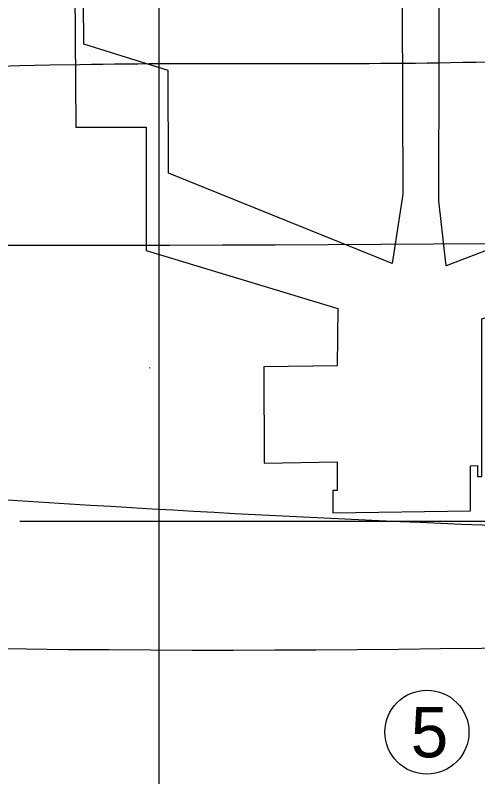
# Model space of a CAD drawing. Extents: x 3042 to 4120, y 576 to 2694.
# Drawn here: x 3407.61 to 3421.37, y 879.91 to 902.59 of the extents above; entities that cross this region are included whole.
import ezdxf

# ---------------------------------------------------------------- set-up
doc = ezdxf.new("R2010")
doc.units = 0
for name, color, linetype in [('HPV', 7, 'Continuous'), ('nádrže', 7, 'Continuous'), ('pomocna', 7, 'Continuous'), ('rozhraní', 7, 'Continuous')]:
    doc.layers.add(name, color=color, linetype=linetype)

msp = doc.modelspace()

# ---------------------------------------------------------------- linework, layer by layer
at = {"layer": 'HPV'}
msp.add_spline([(3335.582962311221, 896.0481503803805), (3352.5717167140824, 896.0481503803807), (3453.0617167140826, 896.509755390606), (3557.3317167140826, 895.7898480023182), (3580.051716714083, 892.4898632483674), (3619.081666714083, 896.3928809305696), (3629.646992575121, 896.3928809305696)], degree=3, dxfattribs=at)
at = {"layer": 'nádrže'}
for points in [[(3409.303423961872, 914.1569885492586), (3409.408686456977, 899.2547771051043), (3411.508241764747, 899.2547771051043), (3411.508241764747, 895.5829811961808), (3417.204521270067, 893.855992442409), (3417.1837969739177, 892.1470730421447), (3415.008440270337, 892.1134452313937), (3415.0102104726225, 889.2506202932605), (3417.18601010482, 889.2842549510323), (3417.186534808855, 888.4356876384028), (3417.053939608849, 888.4336379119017), (3417.054349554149, 887.7706619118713), (3421.1484111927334, 887.8339500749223), (3421.1475844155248, 889.1710393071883), (3421.357533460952, 889.1742848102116), (3421.3577313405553, 888.854267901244), (3421.491589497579, 888.8563371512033), (3421.4886866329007, 893.5509381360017), (3427.7400951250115, 895.7070122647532), (3427.694777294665, 898.9919209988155), (3429.8856289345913, 899.1045903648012), (3429.868067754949, 915.3762984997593)], [(3419.083560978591, 914.0946410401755), (3419.1425912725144, 897.2650842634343), (3418.823963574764, 895.1957636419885), (3412.1724532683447, 897.8815423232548), (3412.161788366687, 900.9398904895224), (3409.6512038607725, 901.7310102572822), (3409.548831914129, 914.2950201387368)], [(3429.622937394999, 914.1473342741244), (3429.636484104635, 901.5953241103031), (3426.981026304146, 901.0790037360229), (3427.0099394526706, 897.3614647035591), (3426.878417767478, 897.3358919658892), (3426.8764187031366, 897.5929238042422), (3420.4257778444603, 895.1284495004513), (3420.208036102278, 897.0576981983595), (3420.2523620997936, 914.1558991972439)]]:
    msp.add_lwpolyline(points, dxfattribs=at)
at = {"layer": 'pomocna'}
msp.add_line((3411.891716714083, 864.8590620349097), (3411.891716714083, 917.8590620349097), dxfattribs=at)
at = {"layer": 'rozhraní'}
msp.add_circle((3419.8549435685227, 881.2381839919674), 1.25, dxfattribs=at)
for points in [[(3442.2980689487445, 897.9504925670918), (3431.3317167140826, 901.5090620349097), (3430.030343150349, 901.4533469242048), (3426.6579803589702, 901.3354072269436), (3420.5505789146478, 901.1702916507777), (3409.5313912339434, 901.1164816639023), (3352.5717167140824, 896.4090620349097), (3327.8662573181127, 896.5362487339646)], [(3248.313660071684, 891.8591120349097), (3256.3217167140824, 891.8591120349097), (3352.5717167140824, 886.4090620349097), (3431.331691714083, 884.0090620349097), (3453.0617167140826, 885.4090620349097), (3491.5217167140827, 887.3591120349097), (3557.3317167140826, 884.6590620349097), (3580.051716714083, 895.0090120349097), (3619.0817167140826, 891.2590620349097), (3629.2745825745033, 891.2590620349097)], [(3411.598810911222, 892.0960254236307), (3411.598872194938, 892.0958822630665), (3411.6067048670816, 892.0775578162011)], [(3327.731251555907, 891.6486311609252), (3352.6357167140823, 891.4090620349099), (3372.3327436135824, 890.6912689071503), (3392.0153061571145, 889.3178217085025), (3411.682073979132, 887.8899946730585), (3431.3317167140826, 887.0090620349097), (3453.0617167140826, 886.9090620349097), (3491.5217167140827, 891.3591120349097), (3507.9473907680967, 889.8031245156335), (3524.476644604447, 888.6483564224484), (3540.9809344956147, 888.0489536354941), (3549.183548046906, 888.005684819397), (3553.26544223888, 888.0565884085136), (3557.3317167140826, 888.1590620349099), (3567.4684942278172, 889.0537677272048)], [(3518.8092174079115, 887.5130386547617), (3431.6794431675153, 887.5130386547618), (3407.745558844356, 887.5130386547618)], [(3311.776722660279, 872.8264542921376), (3352.5717167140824, 872.4090620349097), (3453.0617167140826, 876.9090620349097), (3491.5217167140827, 872.8591120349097), (3557.3317167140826, 880.1590620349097), (3580.051716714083, 879.0090120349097), (3619.0817167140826, 872.7591120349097), (3628.716834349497, 873.2727391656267)]]:
    msp.add_spline(points, degree=3, dxfattribs=at)

# ---------------------------------------------------------------- texts
msp.add_text('5', height=1.5, dxfattribs=at).set_placement((3419.373913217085, 880.4881839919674))

doc.saveas('drawing.dxf')
